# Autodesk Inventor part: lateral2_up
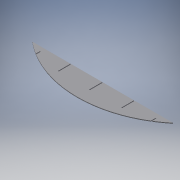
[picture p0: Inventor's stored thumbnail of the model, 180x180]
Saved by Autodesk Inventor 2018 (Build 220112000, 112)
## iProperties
Created: 2019-03
Part Number: lateral2_up
Material: Generic
Document SubType Name: Modeling
Designer: vpimentel
Density: 1 g/cm^3
Appearance: Default
Author: vpimentel
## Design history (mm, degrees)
sketch "Sketch1"
  geometry: L1 (-273.55, 47.108)-(276.45, 47.108) reference; L2 (0, 0)-(2.9, 0) reference; L3 (-273.55, 47.108)-(276.45, 47.108) reference; L4 (-205.8, 21.451)-(-205.8, -4.801) reference; L5 (-202.9, 21.451)-(-205.8, 21.451) reference; L6 (-202.9, -6.549)-(-202.9, 21.451) reference; L7 (-112.9, 0)-(-112.9, -46.144) reference; L8 (-110, 0)-(-112.9, 0) reference; L9 (-110, -47)-(-110, 0) reference; L10 (0, -7.889)-(0, -62.889) reference; L11 (2.9, -7.889)-(0, -7.889) reference; L12 (2.9, -62.889)-(2.9, -7.889) reference; L13 (112.9, 0)-(112.9, -47) reference; L14 (115.8, 0)-(112.9, 0) reference; L15 (115.8, -46.144)-(115.8, 0) reference; L16 (205.8, 21.451)-(205.8, -6.549) reference; L17 (208.7, 21.451)-(205.8, 21.451) reference; L18 (208.7, -4.801)-(208.7, 21.451) reference; L19 (1.45, 47.108)-(1.45, -42.892); L20 (0, 47.108)-(0, 0); L21 (0, 0)-(2.9, 0); L22 (2.9, 0)-(2.9, 47.108); L23 (-110, 2.108)-(-112.9, 2.108) reference; L24 (115.8, 2.108)-(112.9, 2.108) reference; L25 (112.9, 47.108)-(112.9, 2.108); L26 (112.9, 2.108)-(115.8, 2.108); L27 (115.8, 2.108)-(115.8, 47.108); L28 (-112.9, 47.108)-(-112.9, 2.108); L29 (-112.9, 2.108)-(-110, 2.108); L30 (-110, 2.108)-(-110, 47.108); L31 (205.8, 14.548)-(208.7, 14.548); L32 (208.7, 16.335)-(208.7, 31.548); L33 (208.7, 31.548)-(205.8, 31.548); L34 (205.8, 31.548)-(205.8, 14.548); L35 (-205.8, 16.335)-(-205.8, 31.548); L36 (-205.8, 31.548)-(-202.9, 31.548); L37 (-202.9, 31.548)-(-202.9, 14.548); L38 (251.45, 47.108)-(115.8, 47.108); L39 (112.9, 47.108)-(2.9, 47.108); L40 (0, 47.108)-(-110, 47.108); L41 (-112.9, 47.108)-(-248.55, 47.108); A1 r 398.75 centre (1.45, 335.858) between (-273.55, 47.108) and (-205.8, -4.801) reference; A2 r 398.75 centre (1.45, 335.858) between (-202.9, -6.549) and (-112.9, -46.144) reference; A3 r 398.75 centre (1.45, 335.858) between (-110, -47) and (0, -62.889) reference; A4 r 398.75 centre (1.45, 335.858) between (2.9, -62.889) and (112.9, -47) reference; A5 r 398.75 centre (1.45, 335.858) between (115.8, -46.144) and (205.8, -6.549) reference; A6 r 398.75 centre (1.45, 335.858) between (208.7, -4.801) and (276.45, 47.108) reference; A7 r 392.222 centre (1.45, 349.33) between (208.7, 16.335) and (251.45, 47.108); A8 r 392.222 centre (1.45, 349.33) between (-248.55, 47.108) and (-205.8, 16.335); A9 r 392.222 centre (1.45, 349.33) between (-202.9, 14.548) and (205.8, 14.548); 1 further point
  constraints: 42 end point, 7 parallel, 7 point on circle, 5 horizontal, 3 centre point, 2 midpoint, 2 point on line, 1 coincident, 1 perpendicular
  dimensions: "d5" = 90 distance of L19.start L19.end; "d6" = 500 distance of L38.start L41.end; "d7" = 17 distance of L33.end L31.start; "d9" = 17 distance of L36.end L37.end; "d10" = 2.9 distance between parallel lines of L10 L12 (derived)
extrude "Extrusion1" new body sketch "Sketch1" distance "d11" = 2.9 (= d10); taper "d12" = 0 deg
body "Solid1"
node "Reference1"
node "Reference2"
node "Reference3"
node "Reference4"
node "Reference5"
